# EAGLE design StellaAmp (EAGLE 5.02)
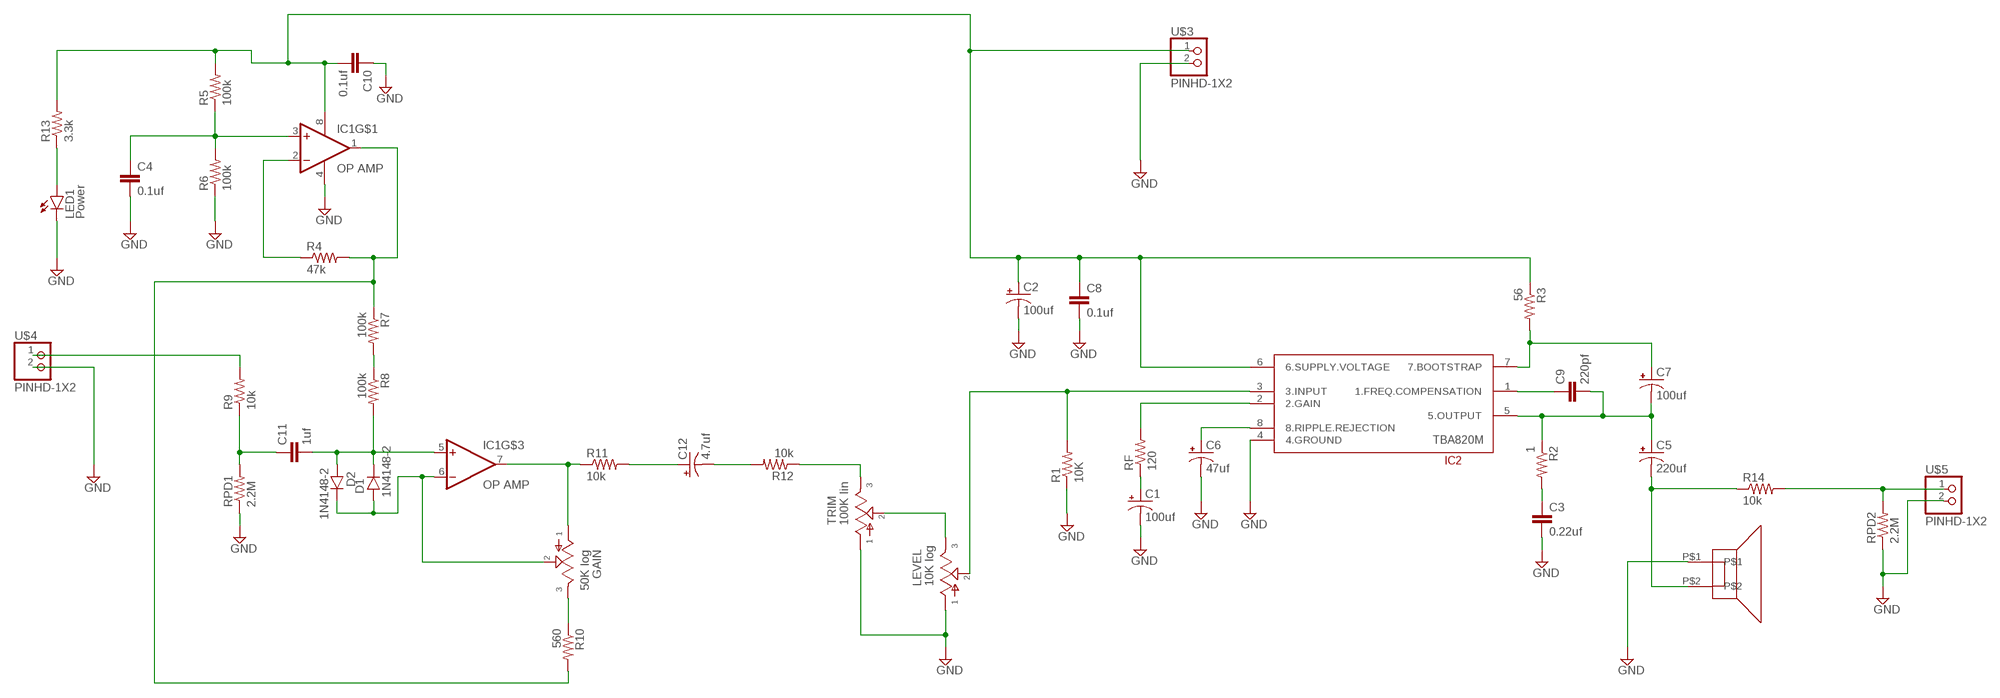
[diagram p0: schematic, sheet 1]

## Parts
C1  100uf  0501  [050_020_1]
C2  100uf  0501  [050_020_1]
C3  0.22uf  075X0303  [075X030_3]
C4  0.1uf  050X030_0251  [050X030_025]
C5  220uf  0802  [080_035_2]
C6  47uf  0501  [050_020_1]
C7  100uf  0501  [050_020_1]
C8  0.1uf  050X030_0251  [050X030_025]
C9  220pf  050X030_0253  [050X030_025_3]
C10  0.1uf  050X030_0251  [050X030_025]
C11  1uf  050X030_0502  [050X030_050]
C12  4.7uf  0501  [050_020_1]
D1  1N4148-2  [DO35-2]
D2  1N4148-2  [DO35-2]
GAIN  50K log  PANAPOT  [PANASONICPOT]
IC1  OP AMP  TS922  [DIL08]
IC2  TBA820M  [DIL08]
LED1  Power  LED3MM  [LED3MM]
LEVEL  10K log  PANAPOT  [PANASONICPOT]
R1  10K  6MM.1  [R0207/1V]
R2  1  6MM.1  [R0207/1V]
R3  56  6MM.3  [R0207/3]
R4  47k  6MM.3  [R0207/3]
R5  100k  6MM.3  [R0207/3]
R6  100k  6MM.3  [R0207/3]
R7  100k  6MM.3  [R0207/3]
R8  100k  6MM.3  [R0207/3]
R9  10k  6MM.3  [R0207/3]
R10  560  6MM.3  [R0207/3]
R11  10k  6MM.3  [R0207/3]
R12  10k  6MM.3  [R0207/3]
R13  3.3k  6MM.3  [R0207/3]
R14  10k  6MM.3  [R0207/3]
RF  120  6MM.3  [R0207/3]
RPD1  2.2M  6MM.3  [R0207/3]
RPD2  2.2M  6MM.3  [R0207/3]
TRIM  100K lin  CTSPOT  [CTS100K]
U$1  SPKR_TERMINAL  [SCREWTERMINALS_2]
U$3  PINHD-1X2  [1X02]
U$4  PINHD-1X2  [1X02]
U$5  PINHD-1X2  [1X02]

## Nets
$N25: C11.1 R9.1 RPD1.2
AMPOUTPUT: C5.+ C7.- C9.2 IC2.5(5.OUTPUT) R2.1
GND: C1.- C2.- C3.2 C4.2 C6.- C8.2 C10.1 IC1.4(V-) IC2.4(4.GROUND) LED1.K(C) LEVEL.P$1 R1.1 R6.1 RPD1.1 RPD2.1 TRIM.P$1 U$1.P$1 U$3.2 U$4.2 U$5.2
N$1: IC2.2(2.GAIN) RF.2
N$2: C7.+ IC2.7(7.BOOTSTRAP) R3.2
N$3: C3.1 R2.2
N$4: IC2.3(3.INPUT) LEVEL.P$2 R1.2
N$5: C1.+ RF.1
N$6: LED1.A R13.1
N$7: C6.+ IC2.8(8.RIPPLE.REJECTION)
N$8: GAIN.P$3 R10.1
N$9: R14.2 RPD2.2 U$5.1
N$10: C9.1 IC2.1(1.FREQ.COMPENSATION)
N$11: C4.1 IC1.3(+IN) R5.1 R6.2
N$12: C12.- R12.2
N$13: GAIN.P$1 IC1.7(OUT) R11.1
N$14: IC1.2(-IN) R4.1
N$16: R9.2 U$4.1
N$17: R12.1 TRIM.P$3
N$18: D1.A D2.C GAIN.P$2 IC1.6(-IN)
N$20: C11.2 D1.C D2.A IC1.5(+IN) R8.2
N$21: C12.+ R11.2
N$22: LEVEL.P$3 TRIM.P$2
N$23: R7.2 R8.1
SPEAKEROUTPUT: C5.- R14.1 U$1.P$2
VCC: C2.+ C8.1 C10.2 IC1.8(V+) IC2.6(6.SUPPLY.VOLTAGE) R3.1 R5.2 R13.2 U$3.1
VCC/2: IC1.1(OUT) R4.2 R7.1 R10.2

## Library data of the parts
C1 C2 C6 C7 C12 = gm-caps-electro-pol:050: 0.22 - 100uF
C3 = CBA awesome:075X030: 0.015 - 0.022uF
C4 C8-C10 = gm-caps-ceramic:050X030_025: 47 - 120pF
C5 = gm-caps-electro-pol:080: 47 - 470uF
C11 = gm-caps-ceramic:050X030_050: 120 - 150pF
D1 D2 = resizeddiode:1N4148: Fast Switching Diode
GAIN LEVEL = Panasonic EVU-F:PANAPOT
IC1 = CBA awesome:TS922
IC2 = CBA awesome:TBA820M
LED1 = gm-diodes:LED
R1-R14 RF RPD1 RPD2 = gm-resistors:6MM: 6mm Resistors
TRIM = Panasonic EVU-F:CTSPOT
U$1 = CBA awesome:SPKR_TERMINAL
U$3-U$5 = CBA awesome:PINHD-1X2

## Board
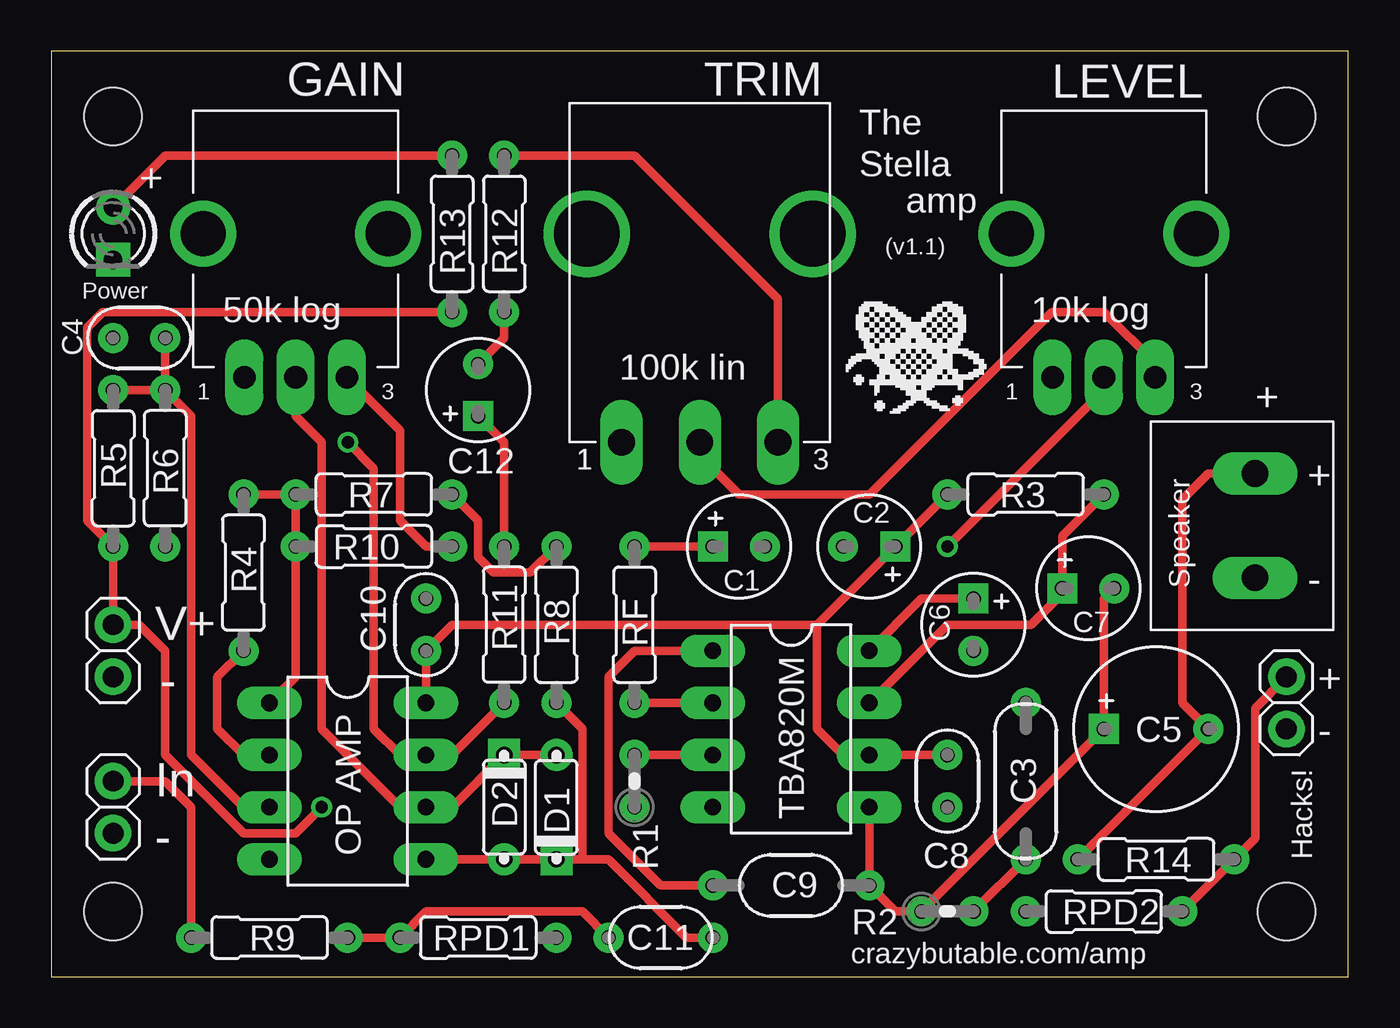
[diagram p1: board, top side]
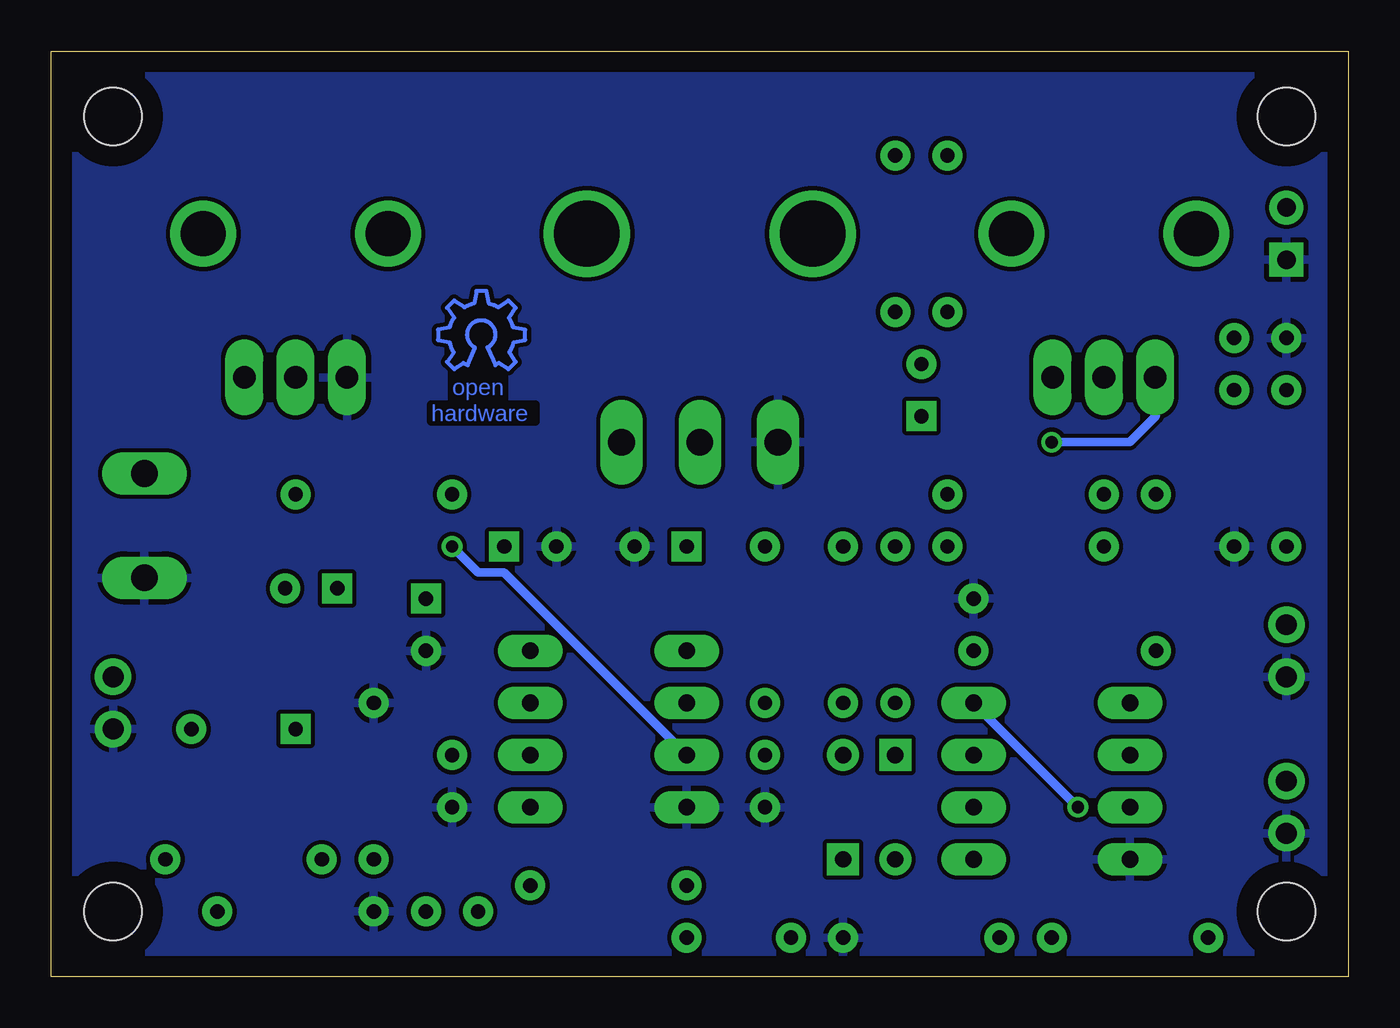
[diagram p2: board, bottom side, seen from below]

Size 63.17 x 45.08 mm. Coordinates in mm from the lower left corner, seen from the top.
Outline: 0,0 63.17,0 63.17,45.08 0,45.08 0,0
Copper layers (1*16): Top 0.035mm / dielectric 1.5mm / Bottom 0.035mm
Design rules "default *": minimum track width 10mil, minimum drill 24mil, track to track 8mil, track to pad 8mil, pad to pad 8mil, via to via 8mil, smd to smd 8mil, copper to edge 40mil, drill to drill 8mil, minimum pad ring 15mil, minimum via ring 8mil, stop-mask expansion 4mil, vias tented up to drill 0mil, thermal gap 10mil
Holes 2.8 mm at 3.01,3.17 3.01,41.91 60.16,3.17 60.16,41.91

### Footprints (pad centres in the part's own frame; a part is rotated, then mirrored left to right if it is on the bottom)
050_020_1 = drill 0.7 square: + -1.27,0 | drill 0.7 round: - 1.27,0
075X030_3 = drill 0.7 round: 1 -3.81,0; 2 3.81,0
050X030_025 = drill 0.7 round: 1 -1.27,0; 2 1.27,0
080_035_2 = drill 0.7 square: + -2.54,0 | drill 0.7 round: - 2.54,0
050X030_025_3 = drill 0.7 round: 1 -3.81,0; 2 3.81,0
050X030_050 = drill 0.7 round: 1 -2.54,0; 2 2.54,0
DO35-2 = drill 0.8 round: A 2.54,0 | drill 0.8 square: C -2.54,0
PANASONICPOT = drill 1.1 pad 1.422 long: P$1 -2.5,-7; P$2 0,-7; P$3 2.5,-7 | drill 2.2 round: STRAINRELIEF1 -4.5,0; STRAINRELIEF2 4.5,0
DIL08 = drill 0.813 long: 1 -3.81,-3.81; 2 -1.27,-3.81; 3 1.27,-3.81; 4 3.81,-3.81; 5 3.81,3.81; 6 1.27,3.81; 7 -1.27,3.81; 8 -3.81,3.81
LED3MM = drill 0.9 round: A -1.27,0 | drill 0.9 square: K 1.27,0
R0207/1V = drill 0.7 round: 1 -1.27,0; 2 1.27,0
R0207/3 = drill 0.7 round: 1 -3.81,0; 2 3.81,0
CTS100K = drill 1.3 long: P$1 -3.81,-10.16; P$2 0,-10.16; P$3 3.81,-10.16 | drill 3.2 round: STRAINRELIEF1 -5.5,0; STRAINRELIEF2 5.5,0
SCREWTERMINALS_2 = drill 1.3 long: P$1 -2.54,0; P$2 2.54,0
1X02 = drill 1.016 round: 1 -2.54,0; 2 0,0

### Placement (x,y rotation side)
C1  33.49,20.95 0 top
C2  39.84,20.95 180 top
C3  47.46,9.52 90 top
C4  4.28,31.11 180 top
C5  53.81,12.06 0 top
C6  44.92,17.14 270 top
C7  50.51,18.92 0 top
C8  43.65,9.52 270 top
C9  36.03,4.44 0 top
C10  18.25,17.14 270 top
C11  29.68,1.9 0 top
C12  20.79,28.57 90 top
D1  24.6,8.25 90 top
D2  22.06,8.25 270 top
GAIN  11.9,36.19 0 top
IC1  14.44,9.52 270 top
IC2  36.03,12.06 270 top
LED1  3.01,36.19 270 top
LEVEL  51.27,36.19 0 top
R1  28.41,9.52 90 top
R2  43.65,3.17 0 top
R3  47.46,23.49 0 top
R4  9.36,19.68 90 top
R5  3.01,24.76 270 top
R6  5.55,24.76 90 top
R7  15.71,23.49 0 top
R8  24.6,17.14 270 top
R9  10.63,1.9 180 top
R10  15.71,20.95 180 top
R11  22.06,17.14 90 top
R12  22.06,36.19 270 top
R13  19.52,36.19 270 top
R14  53.81,5.71 0 top
RF  28.41,17.14 270 top
RPD1  20.79,1.9 180 top
RPD2  51.27,3.17 0 top
TRIM  31.58,36.19 0 top
U$1  58.64,21.97 90 top
U$2  [NEWLOGO]  38.82,27.3 0 top
U$3  3.01,14.6 270 top
U$4  3.01,6.98 270 top
U$5  60.16,12.06 270 top
U$15  [OSHW_8X150_NOTEXT]  40.09,29.59 0 top

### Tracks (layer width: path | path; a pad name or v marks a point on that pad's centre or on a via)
$N25
  Top 0.406: R9.1 RPD1.2 18.25,3.17 25.87,3.17 C11.1
AMPOUTPUT
  Top 0.406: IC2.5 C9.2 41.11,3.17 R2.1 C5.+ 51.27,18.41 C7.-
GND
  pour Bottom: 0.47,0.63 0.47,44.45 62.7,44.45 62.7,0.63
  pour Bottom: 0.47,0.63 0.47,44.45 62.7,44.45 62.7,0.63
N$1
  Top 0.406: RF.2 IC2.2
N$2
  Top 0.406: R3.2 49.24,21.46 C7.+ 49.24,18.66 47.71,17.14 43.65,17.14 IC2.7
N$3
  Top 0.406: R2.2 C3.1
N$4  (via drill 0.6)
  Top 0.406: R1.2 IC2.3 | LEVEL.P$2 51.27,28.57 v43.65,20.95
  Bottom 0.406: IC2.3 41.11,19.68 42.38,19.68 v43.65,20.95
N$5
  Top 0.406: RF.1 C1.+
N$6
  Top 0.406: R13.1 5.55,40 LED1.A
N$7
  Top 0.406: C6.+ 42.38,18.41 IC2.8
N$8
  Top 0.406: R10.1 18.25,20.95 16.98,22.22 16.98,26.61 GAIN.P$3
N$9
  Top 0.406: RPD2.2 R14.2 58.64,6.73 58.64,13.08 U$5.1
N$10
  Top 0.406: IC2.1 28.41,15.87 27.14,14.6 27.14,6.98 29.68,4.44 C9.1
N$11
  Top 0.406: R6.2 R5.1 | R6.2 C4.1 | R6.2 6.82,27.3 6.82,10.79 9.36,8.25 IC1.3
N$12
  Top 0.406: R12.2 22.06,31.11 C12.-
N$13  (via drill 0.6)
  Top 0.406: 19.52,10.79 IC1.7 | 19.52,10.79 R11.1 | 19.52,10.79 16.98,10.79 15.71,12.06 15.71,24.76 v14.44,26.03
  Bottom 0.406: GAIN.P$1 9.36,29.15 9.36,27.3 10.63,26.03 v14.44,26.03
N$14
  Top 0.406: IC1.2 9.36,10.79 8.09,12.06 8.09,14.6 R4.1
N$16
  Top 0.406: U$4.1 5.55,9.52 6.82,8.25 R9.2
N$17
  Top 0.406: R12.1 28.41,40 35.39,33.02 TRIM.P$3
N$18
  Top 0.406: D1.A D2.C 19.52,8.25 IC1.6 16.98,8.25 13.17,12.06 13.17,26.03 11.9,27.3 GAIN.P$2
N$20
  Top 0.406: IC1.5 D2.A D1.C 25.87,5.71 | R8.2 25.87,12.06 25.87,5.71 | C11.2 30.95,1.9 27.14,5.71 25.87,5.71
N$21
  Top 0.406: C12.+ 22.06,26.03 R11.2
N$22
  Top 0.406: TRIM.P$2 31.58,25.39 33.49,23.49 39.84,23.49 48.73,32.38 51.27,32.38 53.77,29.88 LEVEL.P$3
N$23
  Top 0.406: R8.1 23.33,19.68 21.55,19.68 20.79,20.44 20.79,22.22 R7.2
SPEAKEROUTPUT
  Top 0.406: R14.1 C5.- 55.08,13.33 55.08,23.24 56.35,24.51 U$1.P$2
VCC  (via drill 0.6)
  Top 0.406: C8.1 IC2.6 38.57,10.79 37.3,12.06 37.3,17.14 | R3.1 C2.+ 37.3,17.14 | IC1.8 C10.2 19.52,17.14 37.3,17.14 | v13.17,8.25 11.9,6.98 9.36,6.98 5.55,10.79 5.55,15.87 4.28,17.14 U$3.1 R5.2 1.74,22.22 1.74,31.62 2.5,32.38 R13.2
  Bottom 0.406: v13.17,8.25 IC1.8
VCC/2
  Top 0.406: IC1.1 11.9,14.6 R7.1 | R7.1 R4.2 | R7.1 R10.2

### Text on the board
Bottom: open | hardware
tPlace: GAIN | TRIM | LEVEL | The | + | Stella | amp | (v1.1) | Power | 50k log | 10k log | 100k lin | + | + | Speaker | - | V+ | - | + | - | In | - | Hacks! | crazybutable.com/amp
